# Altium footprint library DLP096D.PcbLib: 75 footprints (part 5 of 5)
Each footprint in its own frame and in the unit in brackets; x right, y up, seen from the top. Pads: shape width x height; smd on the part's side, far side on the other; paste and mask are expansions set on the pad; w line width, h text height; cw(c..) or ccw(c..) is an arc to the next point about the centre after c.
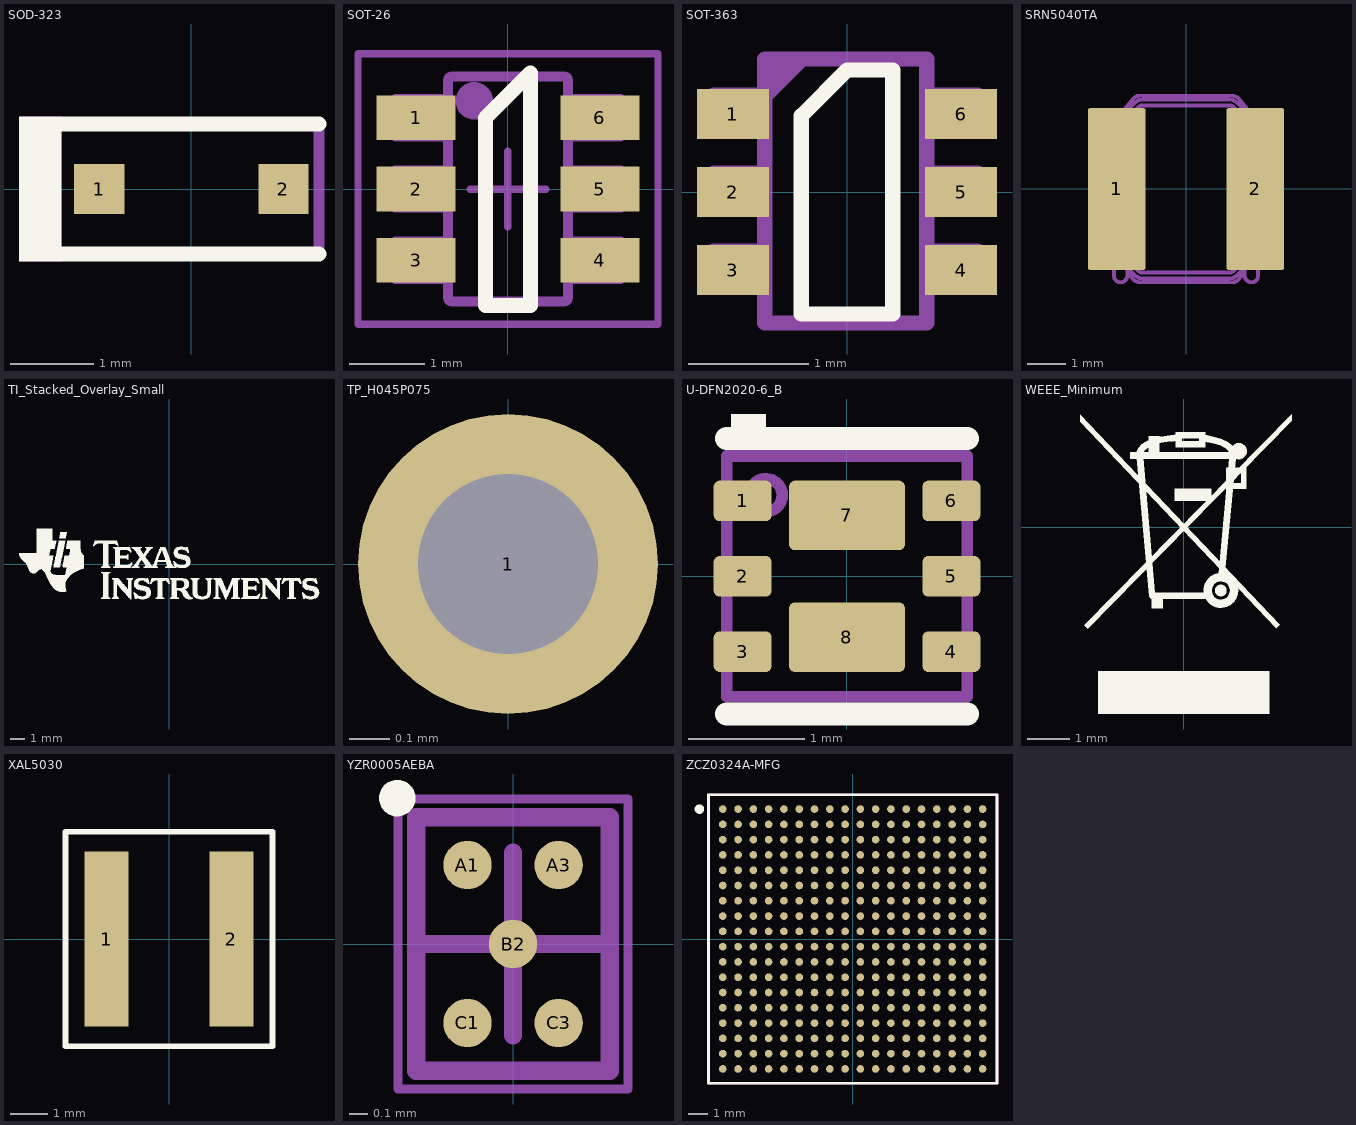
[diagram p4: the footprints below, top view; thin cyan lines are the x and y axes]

## SOD-323 [mm] "NXP recommended land pattern"
height 1.15
pads (2):
  rect 0.6x0.6 smd paste-0.05: 1(-1.1,0) 2(1.1,0)
Top Overlay:
  rectangle: -2.057,-0.864 -1.549,0.864
  lines w0.178: -1.803,-0.775 0.1,-0.775 1.525,-0.775 ; -1.803,0.775 0.1,0.775 1.525,0.775
Mechanical 5:
  rectangle: -2.057,-0.864 -1.549,0.864
  lines w0.127: -1.803,-0.775 0.1,-0.775 1.525,-0.775 1.525,0.775 0.1,0.775 -1.803,0.775
  text ".Designator" at -1.4,-0.275 h0.76
3D body "SOD-323.stp": height 1.1, standoff 0, extent -1.3,-0.675 1.3,0.675

## SOT-26 [mm] "SOT23, 6-Leads, Body 3.1x3.0mm (max), Pitch 0.95mm, IPC Medium Density based on Diodes Inc ap02002.pdf rev 29"
height 1.4
pads (6):
  rect 1.05x0.6 smd: 1(-1.225,0.95) 2(-1.225,0) 3(-1.225,-0.95) 4(1.225,-0.95) 5(1.225,0) 6(1.225,0.95)
Top Overlay:
  lines w0.2: -0.3,-1.55 0.3,-1.55 0.3,1.55 -0.3,0.95 -0.3,-1.55
Mechanical 5:
  circle w0.25: c-0.45,1.175 r0.125
  lines w0.127: -0.8,-1.45 ccw(c-0.75,-1.45) -0.75,-1.5 ; -0.8,-1.45 -0.8,-1.45 ; -0.8,-1.45 -0.8,-1.2 ; -0.8,-1.2 -0.8,-0.7 ; -0.8,-1.2 -0.812,-1.2 -1.109,-1.2 -1.166,-1.2 -1.265,-1.2 -1.5,-1.2 -1.5,-0.7 -1.265,-0.7 -1.166,-0.7 -1.109,-0.7 -0.812,-0.7 -0.8,-0.7 ; -0.8,-0.7 -0.8,-0.25 ; -0.8,-0.25 -0.8,0.25 ; -0.8,-0.25 -0.812,-0.25 -1.109,-0.25 -1.166,-0.25 -1.265,-0.25 -1.5,-0.25 -1.5,0.25 -1.265,0.25 -1.166,0.25 -1.109,0.25 -0.812,0.25 -0.8,0.25 ; -0.8,0.25 -0.8,0.7 ; -0.8,0.7 -0.8,1.2 ; -0.8,0.7 -0.812,0.7 -1.109,0.7 -1.166,0.7 -1.265,0.7 -1.5,0.7 -1.5,1.2 -1.265,1.2 -1.166,1.2 -1.109,1.2 -0.812,1.2 -0.8,1.2 ; -0.8,1.2 -0.8,1.45 ; -0.8,1.45 cw(c-0.75,1.45) -0.75,1.5 ; -0.8,1.45 -0.8,1.45 ; -0.75,-1.5 0.75,-1.5 ; -0.75,-1.5 -0.75,-1.5 ; -0.75,1.5 -0.75,1.5 ; -0.75,1.5 0.75,1.5 ; 0.75,-1.5 ccw(c0.75,-1.45) 0.8,-1.45 ; 0.75,-1.5 0.75,-1.5 ; 0.75,1.5 cw(c0.75,1.45) 0.8,1.45 ; 0.75,1.5 0.75,1.5 ; 0.8,-1.45 0.8,-1.45 ; 0.8,-1.45 0.8,-1.2 ; 0.8,-1.2 0.812,-1.2 1.109,-1.2 1.166,-1.2 1.265,-1.2 1.5,-1.2 1.5,-0.7 1.265,-0.7 1.166,-0.7 1.109,-0.7 0.812,-0.7 0.8,-0.7 ; 0.8,-1.2 0.8,-0.7 ; 0.8,-0.7 0.8,-0.25 ; 0.8,-0.25 0.8,0.25 ; 0.8,-0.25 0.812,-0.25 1.109,-0.25 1.166,-0.25 1.265,-0.25 1.5,-0.25 1.5,0.25 1.265,0.25 1.166,0.25 1.109,0.25 0.812,0.25 0.8,0.25 ; 0.8,0.25 0.8,0.7 ; 0.8,0.7 0.812,0.7 1.109,0.7 1.166,0.7 1.265,0.7 1.5,0.7 1.5,1.2 1.265,1.2 1.166,1.2 1.109,1.2 0.812,1.2 0.8,1.2 ; 0.8,0.7 0.8,1.2 ; 0.8,1.2 0.8,1.45 ; 0.8,1.45 0.8,1.45
  text ".Designator" at -0.125,1.075 h0.64
Mechanical 15:
  lines w0.1: -0.5,0 0.5,0 ; 0,-0.5 0,0.5 ; -2,-1.8 -2,1.8 2,1.8 2,-1.8 -2,-1.8
3D body "SOT23-6.stp": height 1.3, standoff 0, extent -1.5,-1.5 1.5,1.5

## SOT-363 [mm]
pads (6):
  rect 0.6x0.42 smd mask+0.051: 1(-0.95,0.65) 2(-0.95,0) 3(-0.95,-0.65) 4(0.95,-0.65) 5(0.95,0) 6(0.95,0.65)
Top Overlay:
  lines w0.127: -0.381,-1.016 -0.381,0.635 0,1.016 0.381,1.016 0.381,-1.016 -0.381,-1.016
Mechanical 5:
  region: -0.635,1.143 -0.254,1.143 -0.635,0.762
  lines w0.127: -0.686,-0.792 -0.76,-0.792 -0.902,-0.792 -1.111,-0.792 -1.111,-0.492 -0.902,-0.492 -0.76,-0.492 -0.686,-0.492 ; -0.686,-0.142 -0.76,-0.142 -0.902,-0.142 -1.111,-0.142 -1.111,0.158 -0.902,0.158 -0.76,0.158 -0.686,0.158 ; -0.686,0.508 -0.76,0.508 -0.902,0.508 -1.111,0.508 -1.111,0.808 -0.902,0.808 -0.76,0.808 -0.686,0.808 ; 0.664,-0.792 0.738,-0.792 0.88,-0.792 1.089,-0.792 1.089,-0.492 0.88,-0.492 0.738,-0.492 0.664,-0.492 ; 0.664,-0.142 0.738,-0.142 0.88,-0.142 1.089,-0.142 1.089,0.158 0.88,0.158 0.738,0.158 0.664,0.158 ; 0.664,0.508 0.738,0.508 0.88,0.508 1.089,0.508 1.089,0.808 0.88,0.808 0.738,0.808 0.664,0.808 ; -0.686,-1.092 -0.686,1.108 0.664,1.108 0.664,-1.092 -0.686,-1.092
  text ".Designator" at -0.203,0.889 h0.51
3D body "SOT-363.stp": height 1.12, standoff 0.01, extent -1.1,-1.1 1.1,1.1

## SRN5040TA [mm] "Bourns"
height 4.1
pads (2):
  rrect7% 1.5x4.2 smd: 1(-1.8,0) 2(1.8,0)
Mechanical 5:
  drawing of 1117 lines, arcs and shapes, not listed
  text ".Designator" at -1.6,-0.514 h0.8
3D body "SRN5040TA.stp": height 3.81, standoff -0.05, extent -2.425,-2.425 2.425,2.425

## TI_Stacked_Overlay_Small [mm]
Top Overlay:
  drawing of 18 lines, arcs and shapes, not listed

## TP_H045P075 [mm] "TP_H0.45P0.75"
pads (1):
  round 0.75 hole 0.45: 1(0,0)

## U-DFN2020-6_B [mm] "SMD, 6-Leads, Body 2x2mm, Pitch 0.65mm"
height 0.575
pads (8):
  rrect29% 0.5x0.35 smd: 1(-0.9,0.65) 2(-0.9,0) 3(-0.9,-0.65) 4(0.9,-0.65) 5(0.9,0) 6(0.9,0.65)
  rrect17% 1x0.6 smd: 7(0,0.525) 8(0,-0.525)
Top Overlay:
  rectangle: -1,1.2 -0.7,1.4
  lines w0.2: -1.038,-1.188 1.038,-1.188 ; -1.038,1.188 1.038,1.188
Mechanical 5:
  circle w0.1: c-0.7,0.7 r0.141
  lines w0.1: -1.038,-1.037 -1.038,1.038 1.038,1.038 1.038,-1.037 -1.038,-1.037
  text ".Designator" at -0.8,-0.1 h0.4
3D body: height 0.58, standoff 0, extent -1.037,-1.037 1.037,1.037
3D body: height 0.58, standoff 0.58, extent -0.841,0.559 -0.559,0.841

## WEEE_Minimum [mm] "WEEElie bin"
Top Overlay:
  drawing of 23 lines, arcs and shapes, not listed

## XAL5030 [mil] "Coilcraft XAL5030 12/12/11"
height 122.05
pads (2):
  rect 46x183 smd: 1(-65,0) 2(65,0)
Top Overlay:
  lines w6: -108,-112 -108,112 108,112 108,-112 -108,-112
Mechanical 5:
  lines w5: -108,-112 -108,112 108,112 108,-112 -108,-112
  text ".Designator" at -75,-20 h40
3D body: height 122.05, standoff 0, extent -107.98,-111.98 107.98,111.98
3D body: height 122.1, standoff 80, extent 70.02,-49.98 79.98,49.98

## YZR0005AEBA [mm] "Micro SMD, 5-Leads, Body 1.39x1.06mm, Pitch 0.5mm, NSC Recommended"
height 0.68
pads (5):
  round 0.265 smd paste-0.132 mask+0.05: A1(-0.25,0.433) A3(0.25,0.433) B2(0,0) C1(-0.25,-0.433) C3(0.25,-0.433)
Top Overlay:
  circle w0.1: c-0.635,0.8 r0.05
Top Paste:
  circle w0.05: c0.175,0.508 r0.025
  circle w0.05: c0.325,0.358 r0.025
  circle w0.05: c0.325,0.508 r0.025
  circle w0.05: c0.175,0.358 r0.025
  circle w0.05: c-0.325,0.508 r0.025
  circle w0.05: c-0.175,0.358 r0.025
  circle w0.05: c-0.175,0.508 r0.025
  circle w0.05: c-0.325,0.358 r0.025
  circle w0.05: c-0.075,0.075 r0.025
  circle w0.05: c0.075,-0.075 r0.025
  circle w0.05: c0.075,0.075 r0.025
  circle w0.05: c-0.075,-0.075 r0.025
  circle w0.05: c-0.325,-0.358 r0.025
  circle w0.05: c-0.175,-0.508 r0.025
  circle w0.05: c-0.175,-0.358 r0.025
  circle w0.05: c-0.325,-0.508 r0.025
  circle w0.05: c0.175,-0.358 r0.025
  circle w0.05: c0.325,-0.508 r0.025
  circle w0.05: c0.325,-0.358 r0.025
  circle w0.05: c0.175,-0.508 r0.025
  region: 0.325,0.358 0.175,0.358 0.175,0.308 0.325,0.308
  region: 0.325,0.508 0.325,0.358 0.375,0.358 0.375,0.508
  rectangle: 0.175,0.508 0.325,0.558
  region: 0.175,0.358 0.175,0.508 0.125,0.508 0.125,0.358
  region: 0.175,0.508 0.175,0.358 0.325,0.358 0.325,0.508
  region: -0.175,0.358 -0.325,0.358 -0.325,0.308 -0.175,0.308
  region: -0.175,0.508 -0.175,0.358 -0.125,0.358 -0.125,0.508
  rectangle: -0.325,0.508 -0.175,0.558
  region: -0.325,0.358 -0.325,0.508 -0.375,0.508 -0.375,0.358
  region: -0.325,0.508 -0.325,0.358 -0.175,0.358 -0.175,0.508
  region: 0.075,-0.075 -0.075,-0.075 -0.075,-0.125 0.075,-0.125
  region: 0.075,0.075 0.075,-0.075 0.125,-0.075 0.125,0.075
  rectangle: -0.075,0.075 0.075,0.125
  region: -0.075,-0.075 -0.075,0.075 -0.125,0.075 -0.125,-0.075
  region: -0.075,0.075 -0.075,-0.075 0.075,-0.075 0.075,0.075
  region: -0.175,-0.508 -0.325,-0.508 -0.325,-0.558 -0.175,-0.558
  region: -0.175,-0.358 -0.175,-0.508 -0.125,-0.508 -0.125,-0.358
  rectangle: -0.325,-0.358 -0.175,-0.308
  region: -0.325,-0.508 -0.325,-0.358 -0.375,-0.358 -0.375,-0.508
  region: -0.325,-0.358 -0.325,-0.508 -0.175,-0.508 -0.175,-0.358
  region: 0.325,-0.508 0.175,-0.508 0.175,-0.558 0.325,-0.558
  region: 0.325,-0.358 0.325,-0.508 0.375,-0.508 0.375,-0.358
  rectangle: 0.175,-0.358 0.325,-0.308
  region: 0.175,-0.508 0.175,-0.358 0.125,-0.358 0.125,-0.508
  region: 0.175,-0.358 0.175,-0.508 0.325,-0.508 0.325,-0.358
Mechanical 5:
  text ".Designator" at -0.131,0.56 h0.3
Mechanical 13:
  lines w0.1: -0.53,-0.695 0.53,-0.695 0.53,0.695 -0.53,0.695 -0.53,-0.695
Mechanical 15:
  lines w0.05: -0.63,-0.795 0.63,-0.795 0.63,0.795 -0.63,0.795 -0.63,-0.795
  lines w0.1: -0.5,0 0.5,0 ; 0,-0.5 0,0.5
3D body: height 0.68, standoff 0, extent -0.53,-0.695 0.53,0.695

## ZCZ0324A-MFG [mm]
pads (324):
  round 0.4 smd paste+0 mask+0: A1(-6.8,6.8) A2(-6,6.8) A3(-5.2,6.8) A4(-4.4,6.8) A5(-3.6,6.8) A6(-2.8,6.8) A7(-2,6.8) A8(-1.2,6.8) A9(-0.4,6.8) A10(0.4,6.8) A11(1.2,6.8) A12(2,6.8) A13(2.8,6.8) A14(3.6,6.8) A15(4.4,6.8) A16(5.2,6.8) A17(6,6.8) A18(6.8,6.8) B1(-6.8,6) B2(-6,6) B3(-5.2,6) B4(-4.4,6) B5(-3.6,6) B6(-2.8,6) B7(-2,6) B8(-1.2,6) B9(-0.4,6) B10(0.4,6) B11(1.2,6) B12(2,6) B13(2.8,6) B14(3.6,6) B15(4.4,6) B16(5.2,6) B17(6,6) B18(6.8,6) C1(-6.8,5.2) C2(-6,5.2) C3(-5.2,5.2) C4(-4.4,5.2) C5(-3.6,5.2) C6(-2.8,5.2) C7(-2,5.2) C8(-1.2,5.2) C9(-0.4,5.2) C10(0.4,5.2) C11(1.2,5.2) C12(2,5.2) C13(2.8,5.2) C14(3.6,5.2) C15(4.4,5.2) C16(5.2,5.2) C17(6,5.2) C18(6.8,5.2) D1(-6.8,4.4) D2(-6,4.4) D3(-5.2,4.4) D4(-4.4,4.4) D5(-3.6,4.4) D6(-2.8,4.4) D7(-2,4.4) D8(-1.2,4.4) D9(-0.4,4.4) D10(0.4,4.4) D11(1.2,4.4) D12(2,4.4) D13(2.8,4.4) D14(3.6,4.4) D15(4.4,4.4) D16(5.2,4.4) D17(6,4.4) D18(6.8,4.4) E1(-6.8,3.6) E2(-6,3.6) E3(-5.2,3.6) E4(-4.4,3.6) E5(-3.6,3.6) E6(-2.8,3.6) E7(-2,3.6) E8(-1.2,3.6) E9(-0.4,3.6) E10(0.4,3.6) E11(1.2,3.6) E12(2,3.6) E13(2.8,3.6) E14(3.6,3.6) E15(4.4,3.6) E16(5.2,3.6) E17(6,3.6) E18(6.8,3.6) F1(-6.8,2.8) F2(-6,2.8) F3(-5.2,2.8) F4(-4.4,2.8) F5(-3.6,2.8) F6(-2.8,2.8) F7(-2,2.8) F8(-1.2,2.8) F9(-0.4,2.8) F10(0.4,2.8) F11(1.2,2.8) F12(2,2.8) F13(2.8,2.8) F14(3.6,2.8) F15(4.4,2.8) F16(5.2,2.8) F17(6,2.8) F18(6.8,2.8) G1(-6.8,2) G2(-6,2) G3(-5.2,2) G4(-4.4,2) G5(-3.6,2) G6(-2.8,2) G7(-2,2) G8(-1.2,2) G9(-0.4,2) G10(0.4,2) G11(1.2,2) G12(2,2) G13(2.8,2) G14(3.6,2) G15(4.4,2) G16(5.2,2) G17(6,2) G18(6.8,2) H1(-6.8,1.2) H2(-6,1.2) H3(-5.2,1.2) H4(-4.4,1.2) H5(-3.6,1.2) H6(-2.8,1.2) H7(-2,1.2) H8(-1.2,1.2) H9(-0.4,1.2) H10(0.4,1.2) H11(1.2,1.2) H12(2,1.2) H13(2.8,1.2) H14(3.6,1.2) H15(4.4,1.2) H16(5.2,1.2) H17(6,1.2) H18(6.8,1.2) J1(-6.8,0.4) J2(-6,0.4) J3(-5.2,0.4) J4(-4.4,0.4) J5(-3.6,0.4) J6(-2.8,0.4) J7(-2,0.4) J8(-1.2,0.4) J9(-0.4,0.4) J10(0.4,0.4) J11(1.2,0.4) J12(2,0.4) J13(2.8,0.4) J14(3.6,0.4) J15(4.4,0.4) J16(5.2,0.4) J17(6,0.4) J18(6.8,0.4) K1(-6.8,-0.4) K2(-6,-0.4) K3(-5.2,-0.4) K4(-4.4,-0.4) K5(-3.6,-0.4) K6(-2.8,-0.4) K7(-2,-0.4) K8(-1.2,-0.4) K9(-0.4,-0.4) K10(0.4,-0.4) K11(1.2,-0.4) K12(2,-0.4) K13(2.8,-0.4) K14(3.6,-0.4) K15(4.4,-0.4) K16(5.2,-0.4) K17(6,-0.4) K18(6.8,-0.4) L1(-6.8,-1.2) L2(-6,-1.2) L3(-5.2,-1.2) L4(-4.4,-1.2) L5(-3.6,-1.2) L6(-2.8,-1.2) L7(-2,-1.2) L8(-1.2,-1.2) L9(-0.4,-1.2) L10(0.4,-1.2) L11(1.2,-1.2) L12(2,-1.2) L13(2.8,-1.2) L14(3.6,-1.2) L15(4.4,-1.2) L16(5.2,-1.2) L17(6,-1.2) L18(6.8,-1.2) M1(-6.8,-2) M2(-6,-2) M3(-5.2,-2) M4(-4.4,-2) M5(-3.6,-2) M6(-2.8,-2) M7(-2,-2) M8(-1.2,-2) M9(-0.4,-2) M10(0.4,-2) M11(1.2,-2) M12(2,-2) M13(2.8,-2) M14(3.6,-2) M15(4.4,-2) M16(5.2,-2) M17(6,-2) M18(6.8,-2) N1(-6.8,-2.8) N2(-6,-2.8) N3(-5.2,-2.8) N4(-4.4,-2.8) N5(-3.6,-2.8) N6(-2.8,-2.8) N7(-2,-2.8) N8(-1.2,-2.8) N9(-0.4,-2.8) N10(0.4,-2.8) N11(1.2,-2.8) N12(2,-2.8) N13(2.8,-2.8) N14(3.6,-2.8) N15(4.4,-2.8) N16(5.2,-2.8) N17(6,-2.8) N18(6.8,-2.8) P1(-6.8,-3.6) P2(-6,-3.6) P3(-5.2,-3.6) P4(-4.4,-3.6) P5(-3.6,-3.6) P6(-2.8,-3.6) P7(-2,-3.6) P8(-1.2,-3.6) P9(-0.4,-3.6) P10(0.4,-3.6) P11(1.2,-3.6) P12(2,-3.6) P13(2.8,-3.6) P14(3.6,-3.6) P15(4.4,-3.6) P16(5.2,-3.6) P17(6,-3.6) P18(6.8,-3.6) R1(-6.8,-4.4) R2(-6,-4.4) R3(-5.2,-4.4) R4(-4.4,-4.4) R5(-3.6,-4.4) R6(-2.8,-4.4) R7(-2,-4.4) R8(-1.2,-4.4) R9(-0.4,-4.4) R10(0.4,-4.4) R11(1.2,-4.4) R12(2,-4.4) R13(2.8,-4.4) R14(3.6,-4.4) R15(4.4,-4.4) R16(5.2,-4.4) R17(6,-4.4) R18(6.8,-4.4) T1(-6.8,-5.2) T2(-6,-5.2) T3(-5.2,-5.2) T4(-4.4,-5.2) T5(-3.6,-5.2) T6(-2.8,-5.2) T7(-2,-5.2) T8(-1.2,-5.2) T9(-0.4,-5.2) T10(0.4,-5.2) T11(1.2,-5.2) T12(2,-5.2) T13(2.8,-5.2) T14(3.6,-5.2) T15(4.4,-5.2) T16(5.2,-5.2) T17(6,-5.2) T18(6.8,-5.2) U1(-6.8,-6) U2(-6,-6) U3(-5.2,-6) U4(-4.4,-6) U5(-3.6,-6) U6(-2.8,-6) U7(-2,-6) U8(-1.2,-6) U9(-0.4,-6) U10(0.4,-6) U11(1.2,-6) U12(2,-6) U13(2.8,-6) U14(3.6,-6) U15(4.4,-6) U16(5.2,-6) U17(6,-6) U18(6.8,-6) V1(-6.8,-6.8) V2(-6,-6.8) V3(-5.2,-6.8) V4(-4.4,-6.8) V5(-3.6,-6.8) V6(-2.8,-6.8) V7(-2,-6.8) V8(-1.2,-6.8) V9(-0.4,-6.8) V10(0.4,-6.8) V11(1.2,-6.8) V12(2,-6.8) V13(2.8,-6.8) V14(3.6,-6.8) V15(4.4,-6.8) V16(5.2,-6.8) V17(6,-6.8) V18(6.8,-6.8)
Top Overlay:
  circle w0.25: c-8.025,6.8 r0.125
  lines w0.15: -7.55,-7.55 7.55,-7.55 7.55,7.55 -7.55,7.55 -7.55,-7.55
Mechanical 5:
  lines w0.15: -7.55,-7.55 7.55,-7.55 7.55,7.55 -7.55,7.55 -7.55,-7.55
  text ".Designator" at 0.05,0.217 h0.5
3D body "IC_XAM2634AOLFGMZCZQ_NFBGA324.STEP": height 0.25, standoff 0, extent -8.05,-8.05 8.05,8.05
